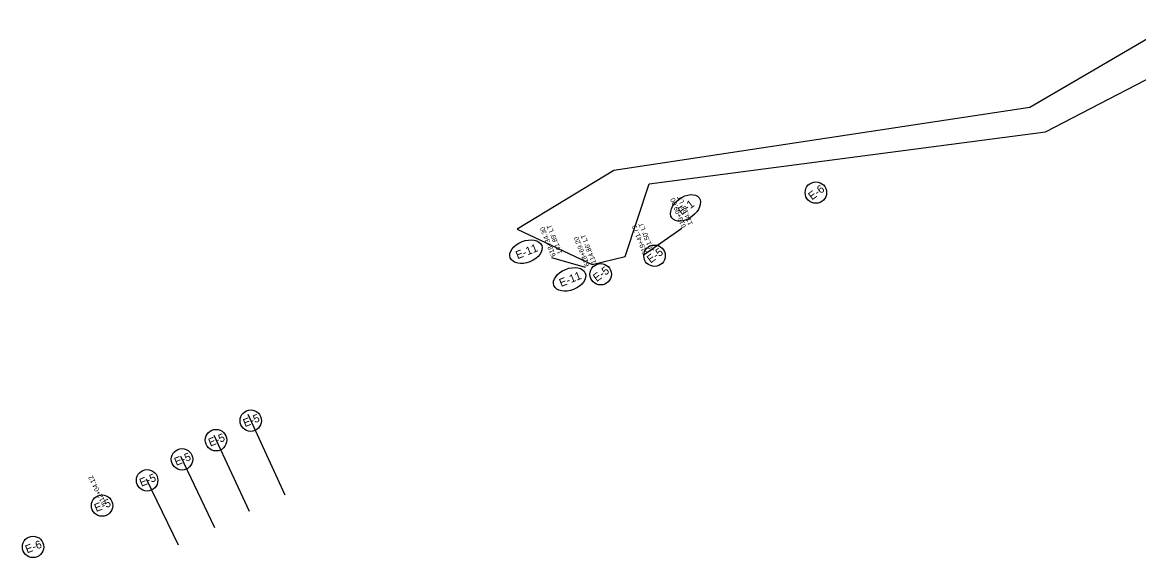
# Model space of a CAD drawing. Extents: x 641687 to 655797, y 406445 to 431088.
# Drawn here: x 641687 to 643082, y 424156 to 424825 of the extents above; entities that cross this region are included whole.
import ezdxf

# ---------------------------------------------------------------- set-up
doc = ezdxf.new("R2010")
doc.units = 0
for name, color, linetype in [('R_Erosion', 7, 'Continuous'), ('R_Erosion_Silt Fence', 7, 'Continuous'), ('R_No Plot', 7, 'Continuous')]:
    doc.layers.add(name, color=color, linetype=linetype)

msp = doc.modelspace()

# ---------------------------------------------------------------- linework, layer by layer
at = {"layer": 'R_Erosion'}
for centre in [(642678.2, 424612.2), (642476.6, 424533.3), (642409.3, 424510.2), (641972.1, 424327.4), (641928.7, 424303), (641886.2, 424279.1), (641842.6, 424252.9), (641786.3, 424221.3), (641700.1, 424169.7)]:
    msp.add_circle(centre, 13.4, dxfattribs=at)
for centre, major_axis in [((642515.3, 424593.1), (16.9, 12.6)), ((642316, 424538.4), (19.6, 7.8)), ((642370.5, 424503.8), (19.6, 7.8))]:
    msp.add_ellipse(centre, major_axis=major_axis, ratio=0.638788, dxfattribs=at)
at = {"layer": 'R_Erosion_Silt Fence'}
for p, q in [((642510.6, 424567.3), (642462.5, 424533.5)), ((642347.7, 424531.2), (642390.1, 424519))]:
    msp.add_line(p, q, dxfattribs=at)
at = {"layer": 'R_No Plot'}
for p, q in [((641968.5, 424335.3), (642014.6, 424234.8)), ((641925.9, 424309.2), (641970.2, 424214.3)), ((641884.3, 424283.1), (641926.7, 424193.8)), ((641841.6, 424254.9), (641881.6, 424172.2))]:
    msp.add_line(p, q, dxfattribs=at)
msp.add_lwpolyline([(643127.7, 424824.8), (642945.5, 424718.3), (642425.7, 424639.9), (642305, 424566.5), (642398.5, 424522.4), (642440.1, 424532.5), (642470, 424623.1), (642965, 424688), (643157.9, 424788.1)], dxfattribs=at)

# ---------------------------------------------------------------- texts
at = {"layer": 'R_Erosion'}
for s, rotation, p in [('E-6', 36.6906, (642673.3, 424602.3)), ('E-1', 36.6906, (642510.6, 424583.5)), ('E-11', 21.657, (642305.5, 424528.9)), ('E-5', 36.6906, (642471.7, 424523.5)), ('E-5', 36.6906, (642404.4, 424500.4)), ('E-11', 21.657, (642359.9, 424494.3)), ('E-5', 21.657, (641964.9, 424319.2)), ('E-5', 21.657, (641921.5, 424294.9)), ('E-5', 21.657, (641879, 424270.9)), ('E-5', 21.657, (641835.4, 424244.8)), ('E-5', 21.657, (641779, 424213.2)), ('E-6', 21.657, (641692.7, 424161.5))]:
    msp.add_text(s, height=10, rotation=rotation, dxfattribs=at).set_placement(p)
at = {"layer": 'R_No Plot'}
for s, rotation, p in [('619+99.00 ', 111.7641, (642516.2, 424569.5)), ("114.98' LT  ", 111.7641, (642524.6, 424572.8)), ("101.50' LT  ", 111.7641, (642476.4, 424539.1)), ('618+34.30 ', 111.7641, (642353.3, 424533.4)), ("141.89' LT  ", 111.7641, (642361.6, 424536.7)), ("114.86' LT  ", 111.7641, (642404.1, 424524.6)), ('619+41.79 ', 111.7641, (642468.1, 424535.8)), ('618+69.20 ', 111.7641, (642395.7, 424521.3)), ('612+04.12 ', 116.2539, (641791.6, 424224))]:
    msp.add_text(s, height=6, rotation=rotation, dxfattribs=at).set_placement(p)

doc.saveas('drawing.dxf')
